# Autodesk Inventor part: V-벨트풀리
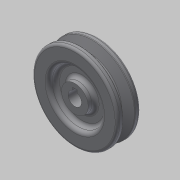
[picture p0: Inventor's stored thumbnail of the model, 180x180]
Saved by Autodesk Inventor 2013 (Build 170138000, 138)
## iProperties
Created: 2015-02
Part Number: V-벨트풀리
Material: 일반
Document SubType Name: Modeling
Designer: Administrator
Density: 1 g/cm^3
Author: Administrator
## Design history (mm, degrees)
sketch "스케치1"
  geometry: L1 (0, 9.5)-(0, -15.5); L2 (5.5, 9.5)-(5.5, -15.5); L3 (5.5, -15.5)-(11, -15.5); L4 (11, -15.5)-(11, -3.5); L5 (11, -3.5)-(21.5, -3.5); L6 (21.5, -3.5)-(21.5, -9.5); L7 (21.5, -9.5)-(35.2, -9.5); L8 (35.2, -9.5)-(35.2, -4.825); L9 (35.2, -4.825)-(26.2, -2.074); L10 (26.2, -2.074)-(26.2, 2.074); L11 (26.2, 2.074)-(35.2, 4.825); L12 (35.2, 4.825)-(35.2, 9.5); L13 (35.2, 9.5)-(21.5, 9.5); L14 (21.5, 9.5)-(21.5, 3.5); L15 (21.5, 3.5)-(11, 3.5); L16 (11, 3.5)-(11, 9.5); L17 (5.5, 9.5)-(11, 9.5); L18 (32.5, 4)-(32.5, -4); 2 further points
  constraints: 36 end point, 10 parallel, 5 equal length, 4 perpendicular, 2 collinear, 2 horizontal alignment, 2 point on line, 1 midpoint, 1 vertical, 1 vertical alignment
  dimensions: "d0" = 9.5 distance of point (0, 0) L1.start; "d1" = 25 distance of L1.start L1.end; "d8" = 34 deg angle of L9 L11; "d9" = 19 distance of L7.end L12.end; "d10" = 8 distance of L18.start L18.end; "d11" = 73 deg angle of L10 L11; "d12" = 6 distance of L15.end L16.end; "d13" = 11 diameter of L2 L1; "d14" = 22 diameter of L16 L1; "d16" = 2.7 distance between parallel lines of L8 L18; "d17" = 6.3 distance between parallel lines of L10 L18; "d18" = 65 diameter of L18 L1; "d19" = 43 diameter of L14 L1
revolve "회전1" sketch "스케치1" stored, may be unused: angle "d20" = 90 deg
sketch "스케치2"
  geometry: L1 (-2, 7.3)-(2, 7.3); L2 (2, 7.3)-(2, 3.3); L3 (2, 3.3)-(-2, 3.3); L4 (-2, 3.3)-(-2, 7.3); C1 r 11 at (0, 0) reference; C2 r 5.5 at (0, 0) reference; 1 further point
  constraints: 8 end point, 2 parallel, 1 horizontal, 1 midpoint, 1 perpendicular, 1 vertical alignment
  dimensions: "d21" = 4 distance of L1.start L1.end; "d23" = 12.8 dimension on C2 L1; "d24" = 4 distance of L1.end L2.end
extrude "돌출1" cut sketch "스케치2" stored distance "d25" = 10; taper "d26" = 0 deg
fillet "모깎기1" dims "d27" = 0.5, "d28" = 1, "d29" = 2
fillet "모깎기2" dims "d30" = 3
node "솔리드1"
